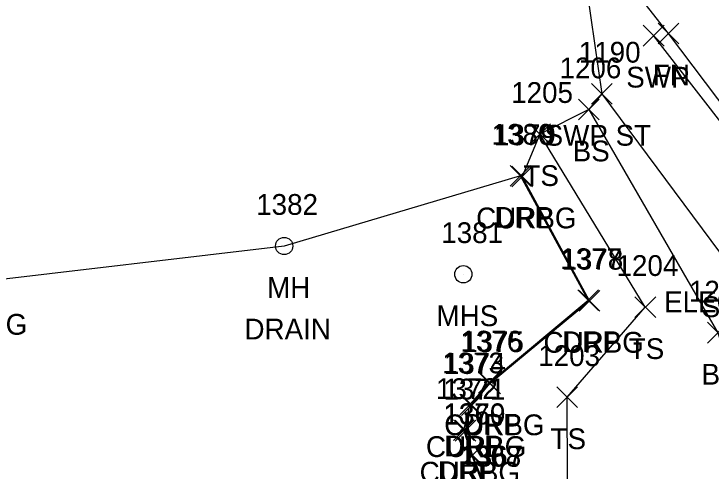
# Model space of a CAD drawing. Extents: x 1715662 to 1717487, y 887396 to 890004.
# Drawn here: x 1716283.7 to 1716350.8, y 888305 to 888349 of the extents above; entities that cross this region are included whole.
import ezdxf

# ---------------------------------------------------------------- set-up
doc = ezdxf.new("R2010")
doc.units = 0
for name, color, linetype in [('L_A', 7, 'Continuous'), ('L_I', 7, 'Continuous'), ('L_TIC', 7, 'Continuous'), ('LELB', 7, 'Continuous'), ('LFNC', 7, 'Continuous'), ('LSOGP', 7, 'Continuous'), ('R_A', 7, 'Continuous'), ('R_I', 7, 'Continuous'), ('R_TIC', 7, 'Continuous'), ('RC', 7, 'Continuous'), ('RDP', 7, 'Continuous'), ('RSW', 7, 'Continuous'), ('U_A', 7, 'Continuous'), ('U_C', 7, 'Continuous'), ('U_I', 7, 'Continuous'), ('USMH', 7, 'Continuous'), ('UUMH', 7, 'Continuous')]:
    doc.layers.add(name, color=color, linetype=linetype)

msp = doc.modelspace()

# ---------------------------------------------------------------- linework, layer by layer
at = {"layer": 'L_TIC'}
for points in [[(1716345.753, 888346.139), (1716347.753, 888348.139)], [(1716347.753, 888346.139), (1716345.753, 888348.139)], [(1716338.091, 888338.822), (1716340.091, 888340.822)], [(1716340.091, 888338.822), (1716338.091, 888340.822)], [(1716333.379, 888336.453), (1716335.379, 888338.453)], [(1716335.379, 888336.453), (1716333.379, 888338.453)], [(1716343.519, 888319.79), (1716345.519, 888321.79)], [(1716345.519, 888319.79), (1716343.519, 888321.79)], [(1716350.492, 888317.326), (1716352.492, 888319.326)], [(1716352.492, 888317.326), (1716350.492, 888319.326)], [(1716335.988, 888311.112), (1716337.988, 888313.112)], [(1716337.988, 888311.112), (1716335.988, 888313.112)]]:
    msp.add_lwpolyline(points, dxfattribs=at)
at = {"layer": 'LELB'}
for points in [[(1716339.091, 888339.822), (1716351.492, 888318.326), (1716356.181, 888303.84), (1716362.768, 888292.5), (1716372.35, 888289.359)], [(1716373.854, 888277.981), (1716341.818, 888277.563), (1716337.074, 888296.382), (1716336.988, 888312.112), (1716344.519, 888320.79), (1716334.379, 888337.453)]]:
    msp.add_lwpolyline(points, dxfattribs=at)
at = {"layer": 'LFNC'}
msp.add_lwpolyline([(1716393.469, 888277.838), (1716385.773, 888290.591), (1716373.292, 888310.5), (1716357.546, 888332.847), (1716346.753, 888347.139), (1716337.883, 888358.435), (1716321.742, 888376.902), (1716305.606, 888393.218), (1716286.544, 888410.885), (1716268.192, 888426.034), (1716248.019, 888441.452), (1716229.393, 888453.959), (1716214.648, 888463.044)], dxfattribs=at)
at = {"layer": 'LSOGP'}
msp.add_lwpolyline([(1716286.539, 888410.877), (1716305.604, 888393.215), (1716321.739, 888376.899), (1716337.876, 888358.43), (1716340.326, 888341.329), (1716339.086, 888339.817), (1716334.375, 888337.45), (1716332.654, 888333.371), (1716332.506, 888333.427), (1716309.755, 888326.671), (1716279.78, 888323.124)], dxfattribs=at)
at = {"layer": 'R_TIC'}
for points in [[(1716344.321, 888345.931), (1716346.321, 888347.931)], [(1716346.321, 888345.931), (1716344.321, 888347.931)], [(1716339.33, 888340.332), (1716341.33, 888342.332)], [(1716341.33, 888340.332), (1716339.33, 888342.332)], [(1716331.507, 888332.43), (1716333.507, 888334.43)], [(1716333.507, 888332.43), (1716331.507, 888334.43)], [(1716331.656, 888332.374), (1716333.656, 888334.374)], [(1716333.656, 888332.374), (1716331.656, 888334.374)], [(1716338.024, 888320.455), (1716340.024, 888322.455)], [(1716340.024, 888320.455), (1716338.024, 888322.455)], [(1716338.139, 888320.4), (1716340.139, 888322.4)], [(1716340.139, 888320.4), (1716338.139, 888322.4)], [(1716328.475, 888312.512), (1716330.475, 888314.512)], [(1716330.475, 888312.512), (1716328.475, 888314.512)], [(1716328.578, 888312.455), (1716330.578, 888314.455)], [(1716330.578, 888312.455), (1716328.578, 888314.455)], [(1716326.66, 888310.412), (1716328.66, 888312.412)], [(1716328.66, 888310.412), (1716326.66, 888312.412)], [(1716326.82, 888310.356), (1716328.82, 888312.356)], [(1716328.82, 888310.356), (1716326.82, 888312.356)], [(1716326.06, 888307.938), (1716328.06, 888309.938)], [(1716328.06, 888307.938), (1716326.06, 888309.938)], [(1716326.215, 888307.893), (1716328.215, 888309.893)], [(1716328.215, 888307.893), (1716326.215, 888309.893)], [(1716326.85, 888305.482), (1716328.85, 888307.482)], [(1716328.85, 888305.482), (1716326.85, 888307.482)], [(1716326.871, 888305.522), (1716328.871, 888307.522)], [(1716328.871, 888305.522), (1716326.871, 888307.522)]]:
    msp.add_lwpolyline(points, dxfattribs=at)
at = {"layer": 'RC'}
msp.add_lwpolyline([(1716337.533, 888268.537), (1716336.051, 888271.2), (1716335.071, 888274.086), (1716334.322, 888279.378), (1716333.482, 888285.082), (1716332.357, 888291.306), (1716331.126, 888297.278), (1716329.548, 888302.44), (1716327.871, 888306.522), (1716327.215, 888308.893), (1716327.82, 888311.356), (1716329.578, 888313.455), (1716339.139, 888321.4), (1716332.656, 888333.374)], dxfattribs=at)
at = {"layer": 'RDP'}
msp.add_lwpolyline([(1716339.044, 888266.533), (1716337.372, 888268.457), (1716335.981, 888271.089), (1716334.899, 888274.075), (1716334.186, 888279.376), (1716333.274, 888285.104), (1716332.288, 888291.299), (1716330.95, 888297.244), (1716329.357, 888302.427), (1716327.85, 888306.482), (1716327.06, 888308.938), (1716327.66, 888311.412), (1716329.475, 888313.512), (1716339.024, 888321.455), (1716332.507, 888333.43)], dxfattribs=at)
at = {"layer": 'RSW'}
for points in [[(1716393.811, 888275.383), (1716384.185, 888289.805), (1716372.137, 888309.995), (1716356.589, 888332.413), (1716345.321, 888346.931)], [(1716340.33, 888341.332), (1716352.583, 888324.821), (1716365.176, 888306.762), (1716377.856, 888286.753), (1716384.363, 888275.19)]]:
    msp.add_lwpolyline(points, dxfattribs=at)
at = {"layer": 'USMH'}
for p, q in [((1716327.004, 888323.957), (1716327.004, 888323.957)), ((1716327.837, 888323.957), (1716327.837, 888323.957))]:
    msp.add_line(p, q, dxfattribs=at)
msp.add_circle((1716327.004, 888323.957), 0.833, dxfattribs=at)
at = {"layer": 'UUMH'}
for p, q in [((1716309.757, 888326.674), (1716309.757, 888326.674)), ((1716310.59, 888326.674), (1716310.59, 888326.674))]:
    msp.add_line(p, q, dxfattribs=at)
msp.add_circle((1716309.757, 888326.674), 0.833, dxfattribs=at)

# ---------------------------------------------------------------- texts
at = {"layer": 'L_A'}
for s, p in [('FN', (1716345.234, 888342.139)), ('BS', (1716337.532, 888334.822)), ('TS', (1716332.789, 888332.453)), ('TS', (1716342.928, 888315.79)), ('BS', (1716349.933, 888313.326)), ('TS', (1716335.397, 888307.112))]:
    msp.add_text(s, height=2, dxfattribs=at).set_placement(p)
at = {"layer": 'L_I'}
for s, p in [('1206', (1716336.264, 888342.822)), ('1205', (1716331.608, 888340.453)), ('1204', (1716341.747, 888323.79)), ('1207', (1716348.721, 888321.326)), ('1203', (1716334.216, 888315.112))]:
    msp.add_text(s, height=2, dxfattribs=at).set_placement(p)
at = {"layer": 'R_A'}
for s, p in [('SWP', (1716342.684, 888341.931)), ('SWP ST', (1716334.826, 888336.332)), ('CURBG', (1716328.239, 888328.374)), ('DRP', (1716329.995, 888328.43)), ('SWP', (1716349.946, 888319.821)), ('CURBG', (1716275.37, 888318.13)), ('CURBG', (1716334.722, 888316.4)), ('DRP', (1716336.512, 888316.455)), ('CURBG', (1716325.161, 888308.455)), ('DRP', (1716326.963, 888308.512)), ('CURBG', (1716323.403, 888306.356)), ('DRP', (1716325.148, 888306.412)), ('CURBG', (1716322.798, 888303.893)), ('DRP', (1716324.548, 888303.938))]:
    msp.add_text(s, height=2, dxfattribs=at).set_placement(p)
at = {"layer": 'R_I'}
for s, p in [('1190', (1716338.117, 888344.332)), ('1380', (1716329.727, 888336.43)), ('1379', (1716329.955, 888336.374)), ('1377', (1716336.331, 888324.455)), ('1378', (1716336.446, 888324.4)), ('1376', (1716326.727, 888316.512)), ('1375', (1716326.885, 888316.455)), ('1373', (1716324.967, 888314.412)), ('1374', (1716325.127, 888314.356)), ('1372', (1716324.367, 888311.938)), ('1371', (1716325.089, 888311.893)), ('1370', (1716325.091, 888309.522)), ('1369', (1716325.102, 888309.482)), ('1368', (1716326.617, 888305.427)), ('1367', (1716326.808, 888305.44))]:
    msp.add_text(s, height=2, dxfattribs=at).set_placement(p)
at = {"layer": 'U_A'}
for s, p in [('MH', (1716308.119, 888321.674)), ('MHS', (1716324.421, 888318.957))]:
    msp.add_text(s, height=2, dxfattribs=at).set_placement(p)
at = {"layer": 'U_C'}
for s, p in [('ELECTRIC', (1716346.325, 888320.299)), ('DRAIN', (1716305.938, 888317.674))]:
    msp.add_text(s, height=2, dxfattribs=at).set_placement(p)
at = {"layer": 'U_I'}
for s, p in [('1382', (1716307.064, 888329.674)), ('1381', (1716324.878, 888326.957))]:
    msp.add_text(s, height=2, dxfattribs=at).set_placement(p)

doc.saveas('drawing.dxf')
